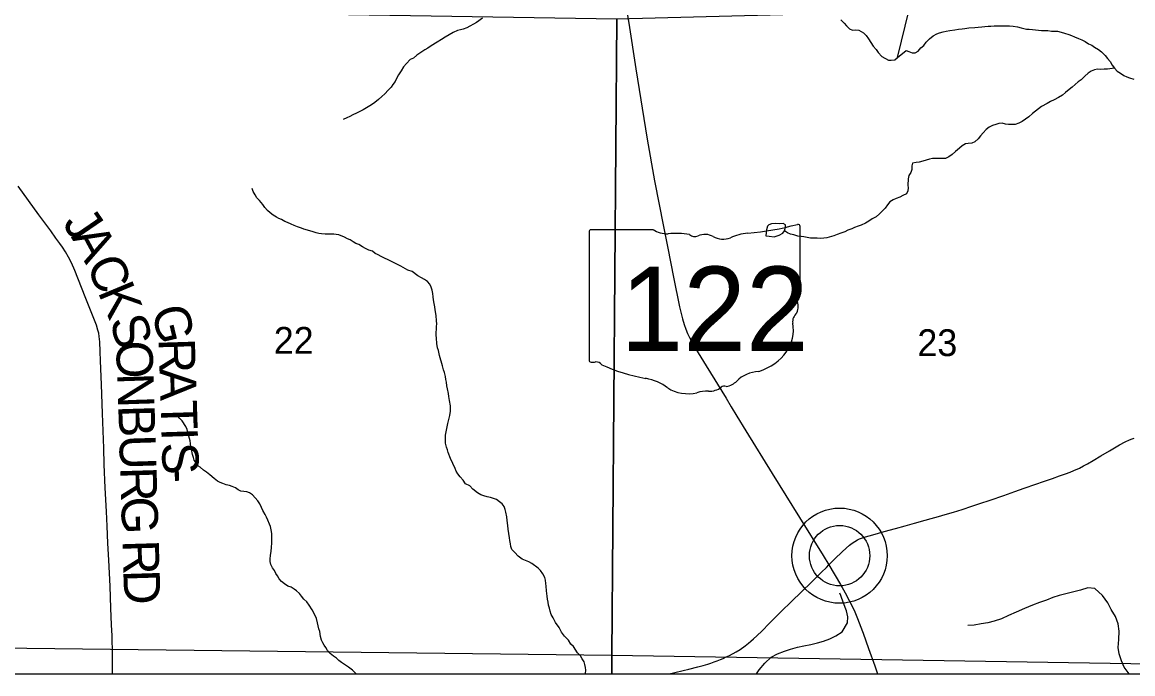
# Model space of a CAD drawing. Extents: x 0 to 34, y 0 to 22.
# Drawn here: x 6.524 to 8.26, y 14.1 to 15.118 of the extents above; entities that cross this region are included whole.
import ezdxf

# ---------------------------------------------------------------- set-up
doc = ezdxf.new("R2010")
doc.units = 0
for name, color, linetype in [('GM_X_Corporation', 7, 'Continuous'), ('GM_X_County_Road', 7, 'Continuous'), ('GM_X_Minor_Lake', 7, 'Continuous'), ('GM_X_Minor_River', 7, 'Continuous'), ('GM_X_Section_Text', 7, 'Continuous'), ('GM_X_State_Location', 7, 'Continuous'), ('GM_X_State_Route', 7, 'Continuous'), ('GM_X_State_Shield', 7, 'Continuous'), ('GM_X_Township_Road', 7, 'Continuous'), ('GM_X_Township_Road_Text', 7, 'Continuous'), ('GM_X_Unincorporated', 7, 'Continuous'), ('GM_X_Unincorporated_Location', 7, 'Continuous'), ('SH_Data', 7, 'Continuous')]:
    doc.layers.add(name, color=color, linetype=linetype)

msp = doc.modelspace()

# ---------------------------------------------------------------- linework, layer by layer
at = {"layer": 'GM_X_Corporation'}
msp.add_lwpolyline([(3.4754, 17.1134), (3.4672, 16.2781), (3.4601, 16.0804), (3.4533, 15.0461), (3.4516, 14.7743), (3.448, 14.3179), (3.4463, 14.1), (8.9, 14.1)], dxfattribs=at)
for points in [[(6.4527, 15.1394), (7.4535, 15.1233), (7.4459, 14.1288), (6.4438, 14.1407)], [(8.4718, 15.1496), (8.4517, 14.1122), (7.4459, 14.1288), (7.4535, 15.1233)], [(6.4436, 14.1), (7.4457, 14.1), (7.4459, 14.1288), (6.4438, 14.1407)], [(7.4457, 14.1), (8.4517, 14.1), (8.4517, 14.1122), (7.4459, 14.1288)]]:
    msp.add_lwpolyline(points, close=True, dxfattribs=at)
at = {"layer": 'GM_X_County_Road'}
for points in [[(7.7847, 14.27), (7.789, 14.2743), (7.7942, 14.2794), (7.8062, 14.2911), (7.817, 14.3008), (7.8211, 14.3042), (7.8253, 14.3069), (7.8294, 14.3091), (7.8329, 14.3106), (7.8372, 14.3123), (7.8422, 14.3139), (7.8534, 14.3173), (7.8714, 14.3221), (7.8888, 14.3269), (7.904, 14.3312), (7.9189, 14.3354), (7.9352, 14.34), (7.9446, 14.3426), (7.956, 14.3459), (7.9666, 14.3489), (7.9795, 14.3527), (7.9933, 14.3568), (8.0081, 14.3616), (8.0208, 14.3658), (8.037, 14.3713), (8.0581, 14.3786), (8.0753, 14.3846), (8.09, 14.3897), (8.1081, 14.3961), (8.12, 14.4002), (8.1344, 14.4052), (8.1452, 14.4091), (8.1545, 14.4124), (8.1617, 14.4152), (8.1676, 14.4175), (8.1764, 14.4214), (8.1829, 14.4247), (8.1889, 14.428), (8.1981, 14.4331), (8.21, 14.4403), (8.2236, 14.4485), (8.2392, 14.4576), (8.2479, 14.4622), (8.2547, 14.4654), (8.2589, 14.467), (8.262, 14.4681)], [(7.5354, 14.1), (7.5439, 14.102), (7.5573, 14.1051), (7.5662, 14.1072), (7.5801, 14.1108), (7.5882, 14.113), (7.5956, 14.1152), (7.6006, 14.1168), (7.6057, 14.1185), (7.6105, 14.1203), (7.6153, 14.1221), (7.6199, 14.1241), (7.6246, 14.1263), (7.6295, 14.1286), (7.6398, 14.1341), (7.646, 14.1379), (7.6538, 14.1436), (7.6595, 14.1478), (7.6631, 14.151), (7.667, 14.1545), (7.6722, 14.1592), (7.6805, 14.1672), (7.6915, 14.1783), (7.7101, 14.1972), (7.7267, 14.213), (7.7576, 14.2433), (7.7735, 14.2588), (7.7809, 14.266), (7.7847, 14.27)]]:
    msp.add_lwpolyline(points, dxfattribs=at)
at = {"layer": 'GM_X_Minor_Lake'}
msp.add_lwpolyline([(7.8036, 15.1214), (7.8088, 15.1163), (7.8125, 15.1124), (7.8169, 15.1073), (7.8218, 15.1053), (7.8263, 15.1059), (7.8316, 15.1054), (7.8387, 15.1014), (7.8431, 15.0971), (7.8468, 15.092), (7.8541, 15.0804), (7.8585, 15.0754), (7.8621, 15.0707), (7.8676, 15.0641), (7.8781, 15.0585), (7.8823, 15.0584), (7.888, 15.0593), (7.8923, 15.0626), (7.9102, 15.1373)], dxfattribs=at)
at = {"layer": 'GM_X_Minor_River'}
for points in [[(7.2437, 15.1242), (7.2344, 15.1176), (7.2297, 15.1147), (7.224, 15.1115), (7.2193, 15.1089), (7.2136, 15.1072), (7.209, 15.1062), (7.2044, 15.1048), (7.1975, 15.1016), (7.1913, 15.0983), (7.1852, 15.0947), (7.1794, 15.0911), (7.1728, 15.0867), (7.1635, 15.0809), (7.1581, 15.0772), (7.1535, 15.0747), (7.1473, 15.0707), (7.1407, 15.0663), (7.1357, 15.0619), (7.1307, 15.0594), (7.1248, 15.0535), (7.1201, 15.0479), (7.1165, 15.0419), (7.1125, 15.0356), (7.1093, 15.03), (7.1069, 15.0251), (7.1034, 15.0206), (7.1006, 15.0162), (7.0963, 15.0117), (7.0908, 15.0062), (7.0865, 15.0017), (7.0811, 14.9969), (7.0753, 14.9925), (7.0702, 14.9889), (7.0625, 14.9842), (7.0571, 14.9809), (7.0517, 14.9784), (7.0467, 14.9759), (7.0409, 14.973), (7.0363, 14.9708), (7.0313, 14.9683), (7.0259, 14.9658)], [(7.8923, 15.0626), (7.9055, 15.0737), (7.91, 15.072), (7.9152, 15.07), (7.9198, 15.0702), (7.9244, 15.0728), (7.9283, 15.0776), (7.933, 15.0816), (7.9369, 15.0865), (7.942, 15.092), (7.9478, 15.0964), (7.9533, 15.0997), (7.9579, 15.1015), (7.9636, 15.1028), (7.9682, 15.1038), (7.9739, 15.1048), (7.9815, 15.1061), (7.9876, 15.1071), (7.9929, 15.1073), (7.9975, 15.1079), (8.0036, 15.1089), (8.0127, 15.1094), (8.0184, 15.11), (8.0238, 15.1106), (8.0287, 15.1109), (8.0336, 15.1115), (8.0382, 15.1117), (8.0431, 15.112), (8.0515, 15.1121), (8.0572, 15.1123), (8.0625, 15.1122), (8.0671, 15.1121), (8.0727, 15.1115), (8.0795, 15.1106), (8.0852, 15.1089), (8.0935, 15.1071), (8.098, 15.107), (8.1033, 15.1065), (8.1169, 15.105), (8.1272, 15.1047), (8.1325, 15.1041), (8.1374, 15.104), (8.1423, 15.1039), (8.148, 15.1022), (8.1529, 15.1005), (8.1596, 15.0984), (8.1641, 15.0972), (8.1686, 15.0951), (8.175, 15.0923), (8.1803, 15.0903), (8.1851, 15.0875), (8.1907, 15.0843), (8.1956, 15.0818), (8.2, 15.0791), (8.206, 15.0751), (8.2108, 15.0715), (8.2164, 15.0661), (8.22, 15.0614), (8.2244, 15.0563), (8.2277, 15.0509), (8.231, 15.0459), (8.2354, 15.0412), (8.2406, 15.038), (8.2458, 15.0345), (8.2503, 15.0324), (8.2548, 15.0312), (8.2616, 15.0291)], [(8.231, 15.0459), (8.2203, 15.0443), (8.215, 15.0444), (8.2097, 15.0442), (8.2048, 15.0443), (8.1998, 15.0437), (8.1948, 15.0416), (8.1902, 15.0383), (8.1847, 15.0335), (8.1789, 15.0276), (8.1742, 15.0247), (8.1699, 15.0203), (8.1649, 15.0166), (8.1602, 15.0125), (8.1548, 15.0081), (8.1497, 15.0041), (8.1439, 15.0001), (8.137, 14.9965), (8.1312, 14.994), (8.1262, 14.9911), (8.117, 14.986), (8.103, 14.975), (8.0972, 14.9699), (8.0921, 14.9662), (8.0867, 14.9626), (8.0817, 14.9604), (8.076, 14.9583), (8.0703, 14.9581), (8.0653, 14.9582), (8.0608, 14.9587), (8.0559, 14.96), (8.0506, 14.9594), (8.0456, 14.958), (8.0403, 14.9566), (8.0352, 14.9541), (8.0306, 14.9501), (8.0259, 14.9449), (8.0216, 14.9401), (8.018, 14.9356), (8.013, 14.9312), (8.008, 14.9291), (8.0026, 14.9284), (7.9981, 14.9278), (7.9934, 14.9249), (7.9888, 14.9209), (7.9829, 14.9161), (7.9775, 14.9113), (7.9721, 14.9073), (7.9671, 14.9047), (7.9523, 14.9052), (7.947, 14.9049), (7.942, 14.9039), (7.937, 14.9025), (7.9317, 14.9008), (7.9259, 14.8994), (7.921, 14.8988), (7.9157, 14.8978), (7.9144, 14.8933), (7.9146, 14.888), (7.913, 14.8831), (7.9098, 14.8782), (7.9085, 14.8733), (7.9082, 14.8635), (7.9085, 14.8589), (7.9083, 14.8543), (7.9059, 14.8498), (7.9002, 14.847), (7.8955, 14.8444), (7.8902, 14.8423), (7.8852, 14.8402), (7.8802, 14.8373), (7.8766, 14.8328), (7.8727, 14.8276), (7.8688, 14.8232), (7.8637, 14.8187), (7.8586, 14.8139), (7.8525, 14.8107), (7.8471, 14.807), (7.842, 14.8038), (7.8351, 14.8009), (7.8305, 14.7991), (7.8251, 14.797), (7.8205, 14.7953), (7.8144, 14.7928), (7.8098, 14.7902), (7.8036, 14.7881), (7.7979, 14.786), (7.7925, 14.7839), (7.7818, 14.7811), (7.7772, 14.7805), (7.7715, 14.7799), (7.7666, 14.7804), (7.756, 14.7807), (7.7507, 14.7816), (7.7458, 14.7825), (7.7413, 14.783), (7.7364, 14.7836), (7.7303, 14.7856), (7.7247, 14.7869), (7.7202, 14.7886), (7.7154, 14.7921)], [(7.1857, 14.4727), (7.1866, 14.478), (7.1894, 14.4908), (7.1911, 14.4973), (7.1925, 14.5037), (7.1934, 14.5105), (7.1934, 14.5185), (7.1918, 14.5269), (7.1909, 14.5334), (7.1903, 14.5376), (7.189, 14.5449), (7.1877, 14.5498), (7.1872, 14.5556), (7.1862, 14.5598), (7.1856, 14.5644), (7.184, 14.5705), (7.1826, 14.5747), (7.1813, 14.5812), (7.1766, 14.5973), (7.1747, 14.605), (7.1733, 14.6092), (7.1724, 14.6161), (7.1716, 14.6241), (7.171, 14.629), (7.1715, 14.6423), (7.172, 14.6465), (7.1718, 14.6511), (7.171, 14.6599), (7.1698, 14.6683), (7.1692, 14.6732), (7.1679, 14.6786), (7.167, 14.6843), (7.1664, 14.6889), (7.1658, 14.6942), (7.1649, 14.6992), (7.1632, 14.7038), (7.1615, 14.7088), (7.1575, 14.7127), (7.1527, 14.7159), (7.1483, 14.7183), (7.1424, 14.7219), (7.1336, 14.7282), (7.1269, 14.7307), (7.1159, 14.7367), (7.1118, 14.7388), (7.1044, 14.7424), (7.1004, 14.7448), (7.0963, 14.7464), (7.0904, 14.7493), (7.086, 14.7513), (7.0797, 14.7549), (7.0756, 14.7565), (7.0716, 14.7601), (7.0657, 14.7618), (7.0609, 14.7642), (7.0561, 14.767), (7.0502, 14.7706), (7.0458, 14.7722), (7.0417, 14.775), (7.037, 14.7778), (7.0325, 14.7795), (7.0281, 14.7822), (7.0192, 14.7855), (7.0151, 14.7864), (7.011, 14.7869), (7.0068, 14.787), (7.0027, 14.7868), (6.9978, 14.7869), (6.9922, 14.7875), (6.9877, 14.788), (6.9836, 14.7888), (6.9788, 14.7905), (6.9736, 14.7918), (6.9646, 14.7943), (6.9606, 14.796), (6.9543, 14.7984), (6.9491, 14.8005), (6.9447, 14.8025), (6.9387, 14.805), (6.9347, 14.8066), (6.9295, 14.8094), (6.9254, 14.8114), (6.9214, 14.8131), (6.9166, 14.8163), (6.9118, 14.8202), (6.9078, 14.8237), (6.9035, 14.8284), (6.9003, 14.8331), (6.8952, 14.8393), (6.8909, 14.8436), (6.8884, 14.8483), (6.8852, 14.8533), (6.8835, 14.8583)], [(7.687, 14.7889), (7.6865, 14.7843), (7.6914, 14.7838), (7.6993, 14.7824), (7.7074, 14.7852), (7.7128, 14.7885), (7.7154, 14.7921)], [(7.7154, 14.7921), (7.7172, 14.7978), (7.7173, 14.8012), (7.7132, 14.8036), (7.7083, 14.8027), (7.7015, 14.8036), (7.695, 14.8031), (7.6911, 14.8013), (7.6888, 14.7991), (7.6875, 14.7934), (7.687, 14.7889)], [(6.788, 14.4546), (6.787, 14.4596), (6.7867, 14.4637), (6.7857, 14.4676), (6.7829, 14.4768), (6.7819, 14.4814), (6.7801, 14.4863), (6.7743, 14.4949), (6.7706, 14.4988), (6.7669, 14.5031)], [(7.4047, 14.1), (7.4046, 14.1005), (7.4048, 14.1055), (7.4045, 14.1097), (7.4036, 14.1146), (7.4022, 14.1189), (7.3994, 14.1231), (7.3965, 14.1278), (7.3922, 14.1325), (7.3858, 14.1425), (7.3818, 14.1464), (7.3779, 14.1523), (7.3717, 14.1589), (7.3671, 14.1651), (7.3632, 14.1725), (7.3575, 14.1802), (7.354, 14.1876), (7.3508, 14.1926), (7.3491, 14.1976), (7.3481, 14.2026), (7.3468, 14.2072), (7.3462, 14.2117), (7.3452, 14.2163), (7.3447, 14.2213), (7.3441, 14.2255), (7.3438, 14.2297), (7.3433, 14.2369), (7.3427, 14.2411), (7.3418, 14.2461), (7.3408, 14.2503), (7.338, 14.2561), (7.3344, 14.2615), (7.3304, 14.2651), (7.3206, 14.2722), (7.3158, 14.275), (7.311, 14.277), (7.3058, 14.2791), (7.2992, 14.2835), (7.2941, 14.2893), (7.2894, 14.294), (7.2881, 14.299), (7.2871, 14.3032), (7.2865, 14.3082), (7.2859, 14.3124), (7.2838, 14.3257), (7.2829, 14.3318), (7.282, 14.3395), (7.2815, 14.3452), (7.2802, 14.3525), (7.2792, 14.3567), (7.2775, 14.3613), (7.2743, 14.3656), (7.2703, 14.3687), (7.2655, 14.3723), (7.2607, 14.3739), (7.2559, 14.3752), (7.251, 14.3765), (7.2454, 14.3778), (7.241, 14.3795), (7.2358, 14.3826), (7.2285, 14.3882), (7.2238, 14.3936), (7.2172, 14.3969), (7.2132, 14.4023), (7.2086, 14.4078), (7.205, 14.4124), (7.2025, 14.4167), (7.2008, 14.4209), (7.1938, 14.4363), (7.19, 14.4456), (7.189, 14.4498), (7.1873, 14.454), (7.186, 14.4601), (7.1855, 14.4666), (7.1857, 14.4727)], [(7.0459, 14.1), (7.045, 14.1012), (7.0402, 14.1055), (7.0343, 14.1102), (7.0294, 14.1134), (7.0231, 14.1174), (7.019, 14.1209), (7.0153, 14.1244), (7.0109, 14.1276), (7.0057, 14.1319), (7.0013, 14.1366), (6.9987, 14.1408), (6.9962, 14.1447), (6.994, 14.1486), (6.9922, 14.1524), (6.9905, 14.1582), (6.9892, 14.1658), (6.9878, 14.1704), (6.9858, 14.1796), (6.9841, 14.1861), (6.9812, 14.193), (6.9776, 14.2), (6.9725, 14.2073), (6.9689, 14.2124), (6.9645, 14.2167), (6.9608, 14.2213), (6.9575, 14.2252), (6.9531, 14.2295), (6.9493, 14.2323), (6.9445, 14.2351), (6.9392, 14.2371), (6.9344, 14.2403), (6.9296, 14.2443), (6.9259, 14.2485), (6.9234, 14.2528), (6.9208, 14.2567), (6.9187, 14.2613), (6.9154, 14.2656), (6.9129, 14.2706), (6.9115, 14.2752), (6.9116, 14.2797), (6.9125, 14.2846), (6.9131, 14.2915), (6.9136, 14.2975), (6.9142, 14.3043), (6.9146, 14.3192), (6.9133, 14.3249), (6.9123, 14.3299), (6.9105, 14.3337), (6.908, 14.3399), (6.9059, 14.3449), (6.9041, 14.3487), (6.9005, 14.3553), (6.8983, 14.3599), (6.8955, 14.3657), (6.8926, 14.3703), (6.8885, 14.375), (6.8841, 14.3797), (6.8796, 14.3825), (6.8751, 14.3841), (6.8706, 14.3846), (6.8661, 14.3855), (6.8619, 14.3875), (6.8578, 14.3903), (6.8526, 14.3927), (6.8481, 14.394), (6.8432, 14.3953), (6.8379, 14.3973), (6.8334, 14.3986), (6.8297, 14.401), (6.8245, 14.4049), (6.8174, 14.4108), (6.8123, 14.4151), (6.8074, 14.4179), (6.8026, 14.423), (6.7985, 14.425), (6.7967, 14.4289), (6.7931, 14.4339), (6.792, 14.4381), (6.7906, 14.4423), (6.7886, 14.4508), (6.788, 14.4546)], [(8.2541, 14.1), (8.2465, 14.1103), (8.2423, 14.1203), (8.2384, 14.131), (8.2368, 14.1413), (8.2379, 14.1538), (8.2383, 14.1668), (8.2367, 14.1782), (8.2329, 14.1897), (8.226, 14.2005), (8.2209, 14.2106), (8.2125, 14.2222), (8.2007, 14.2332), (8.1897, 14.2342), (8.1782, 14.2308), (8.1656, 14.2277), (8.1549, 14.225), (8.1446, 14.2222), (8.1347, 14.2191), (8.1247, 14.2148), (8.114, 14.2113), (8.1032, 14.207), (8.0905, 14.2021), (8.0775, 14.1964), (8.0656, 14.191), (8.0548, 14.186), (8.0429, 14.1821), (8.033, 14.1798), (8.0227, 14.1778), (8.012, 14.1758), (8.0021, 14.1753)], [(7.672, 14.1), (7.676, 14.1062), (7.685, 14.1166), (7.6948, 14.1258), (7.7044, 14.1312), (7.7155, 14.1351), (7.7251, 14.1386), (7.7358, 14.1414), (7.7457, 14.1437), (7.7564, 14.1457), (7.7671, 14.1485), (7.7767, 14.1509), (7.7863, 14.1548), (7.7959, 14.1594), (7.8055, 14.1656), (7.8139, 14.1794), (7.8145, 14.1889), (7.8122, 14.1985), (7.8076, 14.2104), (7.8037, 14.2223), (7.8019, 14.2257)]]:
    msp.add_lwpolyline(points, dxfattribs=at)
at = {"layer": 'GM_X_State_Route'}
for points in [[(7.4628, 15.1727), (7.4723, 15.1163), (7.4834, 15.0451), (7.501, 14.9354), (7.5126, 14.8699), (7.5263, 14.7986), (7.533, 14.7651), (7.5421, 14.7194), (7.5516, 14.6732), (7.5535, 14.6647), (7.556, 14.6544), (7.5587, 14.6454), (7.5612, 14.6384), (7.564, 14.6314), (7.5675, 14.6241), (7.5711, 14.6178), (7.5763, 14.6083), (7.5933, 14.5808), (7.6242, 14.5306), (7.6324, 14.5169)], [(7.6324, 14.5169), (7.6412, 14.5024), (7.6552, 14.4797), (7.6964, 14.4131), (7.7391, 14.3439), (7.7758, 14.2847), (7.7847, 14.27), (7.8031, 14.2396), (7.8105, 14.2267), (7.8168, 14.2146), (7.8212, 14.2055), (7.8253, 14.1968), (7.8295, 14.1864), (7.8373, 14.1661), (7.8384, 14.1632)], [(7.8384, 14.1632), (7.847, 14.1393), (7.8565, 14.1123), (7.8607, 14.1)]]:
    msp.add_lwpolyline(points, dxfattribs=at)
at = {"layer": 'GM_X_State_Shield'}
for p, q in [((7.4103, 14.7903), (7.4103, 14.5902)), ((7.51, 14.7937), (7.4135, 14.7937)), ((7.7398, 14.694), (7.7398, 14.7987)), ((7.7398, 14.694), (7.7398, 14.694))]:
    msp.add_line(p, q, dxfattribs=at)
for centre, major_axis, start_param, end_param in [((7.414, 14.7907), (0.00382, 0), 1.712693, 3.28349), ((7.533, 14.817), (0.037, 0), 4.042523, 4.731795), ((7.5453, 14.6814), (0.133, 0), 1.404758, 1.657858), ((7.5912, 14.7686), (0.0222, 0), 0.950623, 2.079405), ((7.667, 14.7326), (0.0703, 0), 1.699011, 2.107814), ((7.6224, 15.0666), (0.3495, 0), 4.814394, 5.042369), ((7.7362, 14.7991), (0.00367, 0), 6.141152, 7.989035), ((7.5755, 14.7917), (0.0107, 0), 3.836095, 5.185415), ((7.6198, 14.8003), (0.0267, 0), 4.081561, 5.145723), ((7.739, 14.6863), (0.00568, 0), 1.883978, 3.671073), ((7.7029, 14.6731), (0.0341, 0), 5.934695, 6.695948), ((7.7359, 14.6936), (0.00393, 0), 5.05454, 6.418171), ((7.642, 14.6369), (0.0874, 0), 5.101752, 6.440018), ((7.753, 14.6502), (0.0248, 0), 2.387724, 3.262537), ((7.4141, 14.5897), (0.00385, 0), 3.00124, 4.508301), ((7.4147, 14.6102), (0.0294, 0), 4.665946, 4.897461), ((7.4207, 14.5786), (0.0106, 0), 0.519207, 1.627899), ((7.5545, 14.7584), (0.2524, 0), 4.195997, 4.488961), ((7.4792, 14.5003), (0.079, 0), 0.823519, 1.323587), ((7.6789, 14.534), (0.0479, 0), 1.647645, 2.488434), ((7.5647, 14.5776), (0.0501, 0), 4.026481, 4.996735), ((7.5973, 14.5626), (0.0267, 0), 4.691044, 5.507374), ((7.6214, 14.5433), (0.00752, 0), 1.147584, 2.315152), ((7.6182, 14.5708), (0.0282, 0), 4.937069, 5.64225), ((7.5936, 14.5084), (0.0412, 0), 1.495662, 1.94098)]:
    msp.add_ellipse(centre, major_axis=major_axis, ratio=0.8, start_param=start_param, end_param=end_param, dxfattribs=at)
at = {"layer": 'GM_X_Township_Road'}
msp.add_lwpolyline([(6.6654, 14.1), (6.6656, 14.1301), (6.6646, 14.1592), (6.6638, 14.1766), (6.6629, 14.2027), (6.6616, 14.2368), (6.6597, 14.2777), (6.6583, 14.3038), (6.6572, 14.3304), (6.6561, 14.3534), (6.6541, 14.3906), (6.6526, 14.4271), (6.6516, 14.4526), (6.6497, 14.5066), (6.648, 14.5519), (6.6467, 14.5891), (6.6462, 14.6034), (6.6454, 14.6183), (6.6445, 14.6269), (6.6438, 14.6319), (6.6427, 14.6367), (6.6404, 14.6444), (6.6228, 14.6889), (6.6063, 14.7298), (6.6011, 14.7418), (6.5966, 14.7506), (6.592, 14.7589), (6.5871, 14.7666), (6.5832, 14.7722), (6.5769, 14.7807), (6.5688, 14.7917), (6.5501, 14.8172), (6.5181, 14.8615)], dxfattribs=at)
at = {"layer": 'GM_X_Unincorporated'}
for radius in [0.0744, 0.0472]:
    msp.add_circle((7.8016, 14.2845), radius, dxfattribs=at)
at = {"layer": 'GM_X_Unincorporated_Location'}
msp.add_line((7.8016, 14.2845), (7.8016, 14.2845), dxfattribs=at)
at = {"layer": 'SH_Data'}
msp.add_line((2.1, 14.1), (8.9, 14.1), dxfattribs=at)
msp.add_line((2.1, 14.1), (8.9, 14.1), dxfattribs=at)
msp.add_line((2.1, 14.1), (8.9, 14.1), dxfattribs=at)

# ---------------------------------------------------------------- texts
at = {"layer": 'GM_X_Section_Text'}
for s, p in [('22', (6.9174, 14.5999)), ('23', (7.9232, 14.5963))]:
    msp.add_text(s, height=0.04186, rotation=0, dxfattribs=at).set_placement(p)
at = {"layer": 'GM_X_State_Location'}
for s in ['s', 'r']:
    msp.add_text(s, height=0.000189, dxfattribs=at).set_placement((7.5713, 14.6769))
msp.add_text('122', height=0.000189, rotation=0, dxfattribs=at).set_placement((7.5045, 14.6631))
at = {"layer": 'GM_X_State_Shield'}
msp.add_text('122', height=0.13184, dxfattribs=at).set_placement((7.4592, 14.6043))
at = {"layer": 'GM_X_Township_Road_Text'}
for s, rotation, p in [('J', 304.4157, (6.586, 14.8031)), ('A', 298.4462, (6.6002, 14.7824)), ('C', 293.1786, (6.6235, 14.7397)), ('K', 292.6538, (6.6418, 14.6969)), ('G', 283.409, (6.726, 14.669)), ('S', 286.1565, (6.6605, 14.6524)), ('O', 272.4943, (6.6705, 14.6191)), ('R', 271.8367, (6.7372, 14.6233)), ('N', 271.8089, (6.6727, 14.5693)), ('A', 271.8089, (6.7387, 14.5767)), ('T', 271.811, (6.7403, 14.5267)), ('B', 271.7683, (6.6743, 14.5194)), ('I', 271.8073, (6.7416, 14.4842)), ('U', 271.7689, (6.6757, 14.4727)), ('S', 271.8099, (6.7423, 14.4609)), ('R', 271.7702, (6.6773, 14.4227)), ('-', 271.8132, (6.7436, 14.4226)), ('G', 271.7689, (6.6787, 14.3761)), ('R', 271.7692, (6.6808, 14.3086)), ('D', 271.7693, (6.6822, 14.262))]:
    msp.add_text(s, height=0.0568, rotation=rotation, dxfattribs=at).set_placement(p)

doc.saveas('drawing.dxf')
